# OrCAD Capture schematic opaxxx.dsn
size A
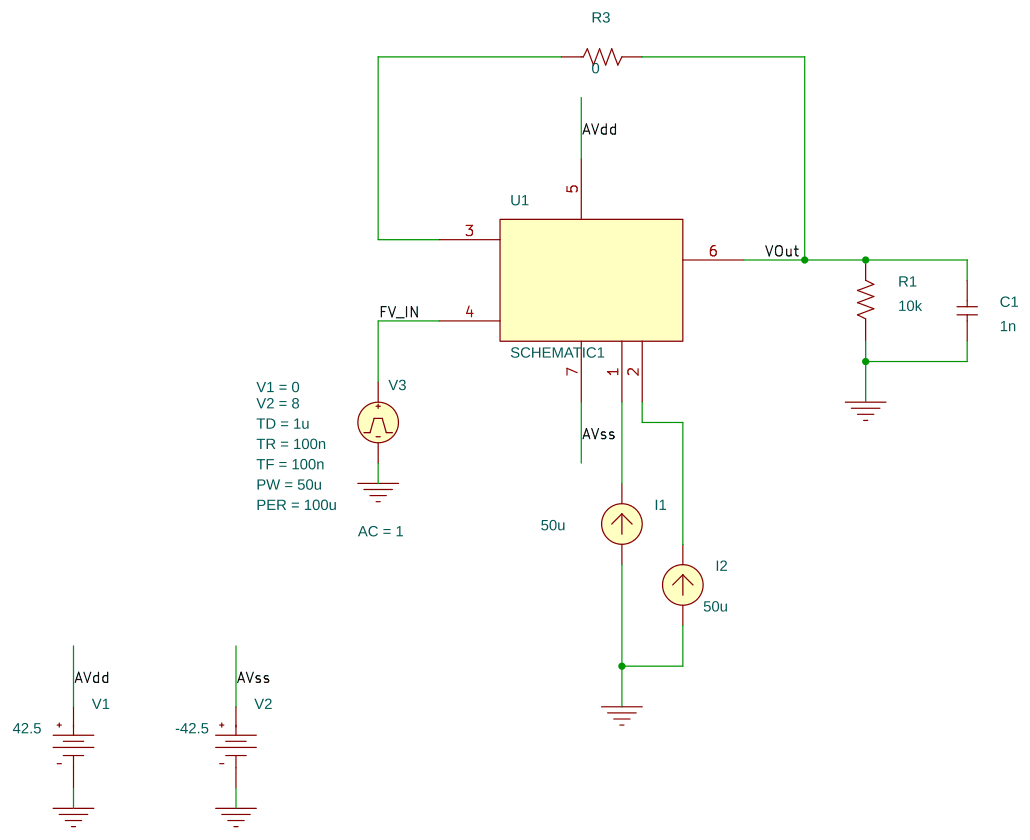
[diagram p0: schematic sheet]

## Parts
C1  1n  [cap196]
I1  IDC
I2  IDC
R1  10k  [AXRC05]
R3  0  [AXRC05]
U1  SCHEMATIC1
V1  VDC
V2  VDC
V3  VPULSE

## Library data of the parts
C1 = C
I1 I2 = IDC: DC: 50u
R1 R3 = R
U1 = SCHEMATIC1
V1 = VDC: DC: 42.5
V2 = VDC: DC: -42.5
V3 = VPULSE: AC: 1; PER: 100u; PW: 50u; TD: 1u; TF: 100n; TR: 100n; V1: 0; V2: 8

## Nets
AVdd: U1.5(VDD) V1.0(+)
AVss: U1.7(VSS) V2.0(+)
0: C1.1 I1.1(+) I2.1(+) R1.1 V1.1(-) V2.1(-) V3.2(-)
FV_IN: U1.4(INP) V3.1(+)
VOut: C1.2 R1.2 R3.2 U1.6(VOUT)
N16278: R3.1 U1.3(INN)
N16408: I1.2(-) U1.1(IBIAS)
N16414: I2.2(-) U1.2(ILIMIT)
